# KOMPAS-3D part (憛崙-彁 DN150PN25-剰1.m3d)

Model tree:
1. Объединить компоненты:1  (labels: СЕНС-ПР DN150PN25-ДП1)

Referenced files in D:\Савин\!СЕНСОР\3D для заказчика\!Новый перечень\СЕНС-ПР\3. СЕНС-ПР-ДП\DN150\СЕНС-ПР DN150PN25-ДП1\: СЕНС-ПР DN150PN25-ДП1.a3d
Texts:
  СЕНС-ПР DN150PN25-ДП1
  ООО НПП Сенсор
  Body Specification ( left align )
  Body Specificaton ( centered )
